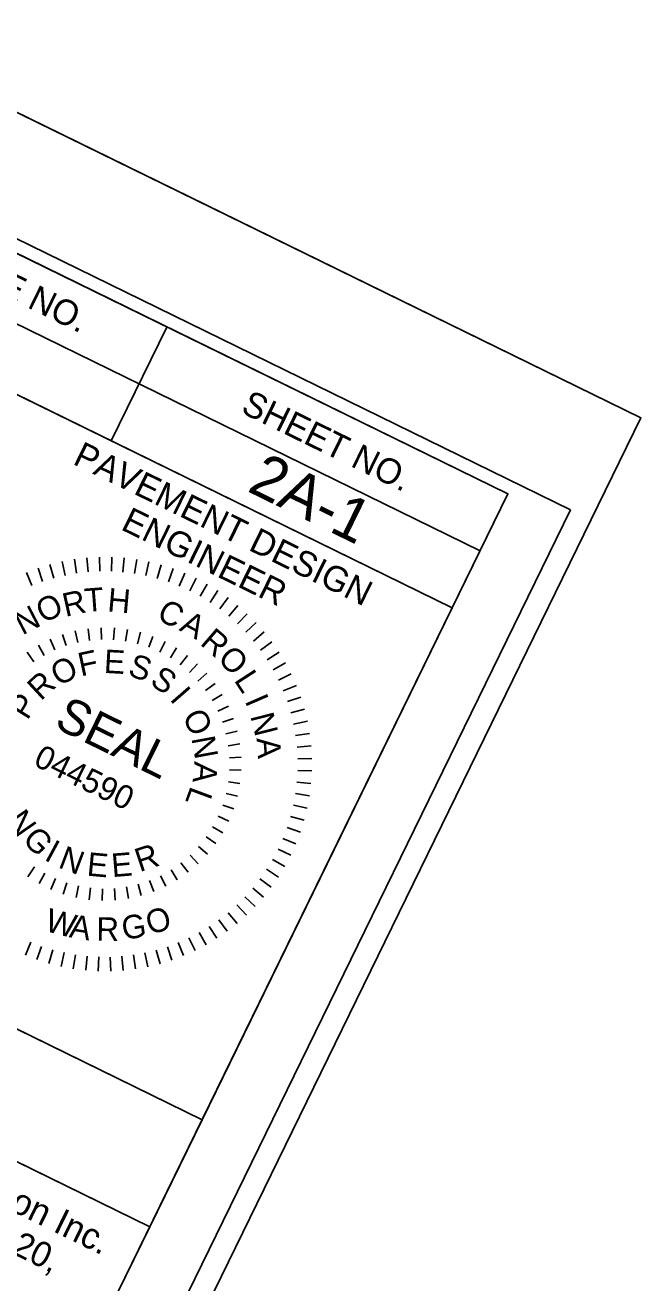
# Model space of a CAD drawing. Extents: x 1518247 to 1523638, y 635234 to 639927.
# Drawn here: x 1522799.6 to 1522921.3, y 639016 to 639264.3 of the extents above; entities that cross this region are included whole.
import ezdxf

# ---------------------------------------------------------------- set-up
doc = ezdxf.new("R2010")
doc.units = 0
for name, color, linetype in [('Default', 7, 'Continuous'), ('DTM TIN Hull White', 7, 'Continuous'), ('Prop Dimension Text', 7, 'Continuous'), ('Sheet Cutting Line CELL', 7, 'Continuous'), ('Sheet Plot Border Inside CELL', 7, 'Continuous'), ('Sheet Plot Border Outside CELL', 7, 'Continuous'), ('Sheet Sticker Exception Certification CELL', 7, 'Continuous'), ('Sheet Typical CELL', 7, 'Continuous')]:
    doc.layers.add(name, color=color, linetype=linetype)

msp = doc.modelspace()

# ---------------------------------------------------------------- linework, layer by layer
at = {"layer": 'Default'}
for points in [[(1522438.02, 638198.63), (1520925.25, 638938.49), (1521408.53, 639926.64), (1522921.3, 639186.78)], [(1522628.72, 639082.58), (1522808.42, 638994.69), (1522824.28, 639027.12), (1522644.58, 639115.01)]]:
    msp.add_lwpolyline(points, close=True, dxfattribs=at)
at = {"layer": 'DTM TIN Hull White'}
for p, q in [((1522806.95, 639158.42), (1522807.53, 639155.69)), ((1522809.38, 639158.86), (1522809.79, 639156.1)), ((1522811.83, 639159.15), (1522812.08, 639156.37)), ((1522814.3, 639159.29), (1522814.37, 639156.5)), ((1522816.76, 639159.28), (1522816.67, 639156.5)), ((1522819.23, 639159.13), (1522818.97, 639156.35)), ((1522821.68, 639158.83), (1522821.25, 639156.07)), ((1522824.11, 639158.37), (1522823.51, 639155.65)), ((1522799.88, 639156.23), (1522800.94, 639153.66)), ((1522802.19, 639157.1), (1522803.09, 639154.47)), ((1522804.55, 639157.83), (1522805.29, 639155.15)), ((1522826.5, 639157.77), (1522825.75, 639155.09)), ((1522828.86, 639157.03), (1522827.94, 639154.4)), ((1522831.16, 639156.15), (1522830.09, 639153.58)), ((1522833.41, 639155.13), (1522832.19, 639152.63)), ((1522835.6, 639153.98), (1522834.22, 639151.55)), ((1522837.7, 639152.69), (1522836.19, 639150.36)), ((1522839.73, 639151.29), (1522838.08, 639149.05)), ((1522841.67, 639149.76), (1522839.89, 639147.62)), ((1522843.52, 639148.12), (1522841.6, 639146.09)), ((1522845.26, 639146.37), (1522843.22, 639144.46)), ((1522807.01, 639144.02), (1522807.73, 639141.81)), ((1522809.52, 639144.72), (1522810.03, 639142.45)), ((1522812.08, 639145.16), (1522812.37, 639142.86)), ((1522814.68, 639145.36), (1522814.74, 639143.04)), ((1522817.28, 639145.31), (1522817.12, 639142.99)), ((1522819.87, 639145), (1522819.48, 639142.71)), ((1522822.41, 639144.45), (1522821.81, 639142.2)), ((1522824.89, 639143.65), (1522824.07, 639141.48)), ((1522846.89, 639144.51), (1522844.75, 639142.73)), ((1522802.25, 639141.93), (1522803.38, 639139.9)), ((1522804.58, 639143.09), (1522805.51, 639140.97)), ((1522827.28, 639142.62), (1522826.26, 639140.53)), ((1522826.26, 639140.53), (1522827.28, 639142.62)), ((1522829.56, 639141.36), (1522828.34, 639139.38)), ((1522848.41, 639142.57), (1522846.16, 639140.92)), ((1522800.04, 639140.55), (1522801.36, 639138.64)), ((1522831.7, 639139.89), (1522830.3, 639138.04)), ((1522849.81, 639140.53), (1522847.46, 639139.03)), ((1522851.08, 639138.41), (1522848.65, 639137.05)), ((1522833.7, 639138.22), (1522832.12, 639136.51)), ((1522835.53, 639136.36), (1522833.79, 639134.81)), ((1522852.22, 639136.23), (1522849.71, 639135.01)), ((1522837.16, 639134.34), (1522835.29, 639132.96)), ((1522853.23, 639133.97), (1522850.65, 639132.91)), ((1522838.6, 639132.16), (1522836.6, 639130.98)), ((1522854.09, 639131.66), (1522851.46, 639130.76)), ((1522839.81, 639129.86), (1522837.71, 639128.88)), ((1522854.82, 639129.3), (1522852.14, 639128.56)), ((1522840.8, 639127.46), (1522838.61, 639126.68)), ((1522855.41, 639126.9), (1522852.68, 639126.32)), ((1522841.55, 639124.96), (1522839.3, 639124.4)), ((1522855.85, 639124.47), (1522853.09, 639124.06)), ((1522842.07, 639122.41), (1522839.77, 639122.06)), ((1522856.14, 639122.02), (1522853.36, 639121.77)), ((1522842.32, 639119.82), (1522840, 639119.7)), ((1522856.28, 639119.55), (1522853.49, 639119.48)), ((1522842.33, 639117.22), (1522840.01, 639117.32)), ((1522856.27, 639117.08), (1522853.49, 639117.18)), ((1522842.09, 639114.62), (1522839.79, 639114.96)), ((1522856.12, 639114.62), (1522853.34, 639114.88)), ((1522841.6, 639112.07), (1522839.34, 639112.62)), ((1522855.82, 639112.17), (1522853.06, 639112.6)), ((1522840.86, 639109.57), (1522838.67, 639110.34)), ((1522855.36, 639109.74), (1522852.64, 639110.34)), ((1522839.89, 639107.16), (1522837.78, 639108.13)), ((1522854.77, 639107.35), (1522852.08, 639108.1)), ((1522835.43, 639104.09), (1522837.32, 639102.74)), ((1522838.69, 639104.85), (1522836.68, 639106.02)), ((1522853.14, 639102.69), (1522850.57, 639103.76)), ((1522854.02, 639104.99), (1522851.39, 639105.91)), ((1522835.64, 639100.63), (1522833.9, 639102.16)), ((1522852.12, 639100.44), (1522849.62, 639101.66)), ((1522831.85, 639097.08), (1522830.43, 639098.92)), ((1522833.83, 639098.76), (1522832.25, 639100.46)), ((1522850.97, 639098.25), (1522848.54, 639099.63)), ((1522800.19, 639096.21), (1522801.5, 639098.12)), ((1522802.41, 639094.84), (1522803.53, 639096.87)), ((1522827.44, 639094.32), (1522826.4, 639096.4)), ((1522829.71, 639095.59), (1522828.48, 639097.56)), ((1522849.68, 639096.14), (1522847.35, 639097.66)), ((1522804.74, 639093.69), (1522805.67, 639095.82)), ((1522807.18, 639092.78), (1522807.89, 639094.99)), ((1522809.7, 639092.1), (1522810.19, 639094.38)), ((1522812.26, 639091.67), (1522812.53, 639093.98)), ((1522814.86, 639091.5), (1522814.91, 639093.82)), ((1522817.46, 639091.57), (1522817.29, 639093.88)), ((1522820.05, 639091.89), (1522819.65, 639094.18)), ((1522822.59, 639092.46), (1522821.97, 639094.7)), ((1522825.06, 639093.27), (1522824.23, 639095.44)), ((1522846.75, 639092.18), (1522844.61, 639093.96)), ((1522848.28, 639094.11), (1522846.04, 639095.77)), ((1522845.11, 639090.33), (1522843.08, 639092.25)), ((1522841.5, 639086.96), (1522839.73, 639089.1)), ((1522843.36, 639088.59), (1522841.45, 639090.63)), ((1522837.52, 639084.04), (1522836.02, 639086.39)), ((1522839.56, 639085.44), (1522837.91, 639087.69)), ((1522833.22, 639081.63), (1522832, 639084.14)), ((1522835.4, 639082.77), (1522834.04, 639085.2)), ((1522799.68, 639080.71), (1522800.75, 639083.28)), ((1522801.98, 639079.83), (1522802.9, 639082.45)), ((1522804.34, 639079.08), (1522805.09, 639081.76)), ((1522826.29, 639079.03), (1522825.55, 639081.71)), ((1522828.65, 639079.76), (1522827.75, 639082.39)), ((1522830.96, 639080.62), (1522829.9, 639083.2)), ((1522806.73, 639078.49), (1522807.33, 639081.21)), ((1522809.16, 639078.03), (1522809.59, 639080.79)), ((1522811.61, 639077.73), (1522811.87, 639080.51)), ((1522814.07, 639077.58), (1522814.17, 639080.36)), ((1522816.54, 639077.57), (1522816.47, 639080.35)), ((1522819.01, 639077.71), (1522818.76, 639080.49)), ((1522821.46, 639078), (1522821.05, 639080.76)), ((1522823.89, 639078.44), (1522823.31, 639081.17))]:
    msp.add_line(p, q, dxfattribs=at)
at = {"layer": 'Sheet Cutting Line CELL'}
msp.add_line((1522921.3, 639186.78), (1521408.53, 639926.64), dxfattribs=at)
at = {"layer": 'Sheet Plot Border Inside CELL'}
msp.add_lwpolyline([(1522907.39, 639168.59), (1521410.35, 639900.76), (1520946.79, 638952.95), (1522443.84, 638220.77)], close=True, dxfattribs=at)
at = {"layer": 'Sheet Plot Border Outside CELL'}
msp.add_lwpolyline([(1522921.3, 639186.78), (1521408.53, 639926.64), (1520925.25, 638938.49), (1522438.02, 638198.63)], close=True, dxfattribs=at)
at = {"layer": 'Sheet Sticker Exception Certification CELL'}
for p, q in [((1522654.9, 639136.12), (1522834.6, 639048.23)), ((1522824.28, 639027.12), (1522644.58, 639115.01)), ((1522834.59, 639048.22), (1522824.27, 639027.11))]:
    msp.add_line(p, q, dxfattribs=at)
at = {"layer": 'Sheet Typical CELL'}
for p, q in [((1522709.82, 639248.41), (1522889.53, 639160.52)), ((1522827.65, 639204.7), (1522816.66, 639182.24))]:
    msp.add_line(p, q, dxfattribs=at)
for points in [[(1522895.04, 639171.79), (1521547.57, 639830.81), (1521086.25, 638887.58), (1522433.73, 638228.56)], [(1522715.33, 639259.68), (1522895.04, 639171.79), (1522884.04, 639149.29), (1522704.33, 639237.18)], [(1522794.21, 639193.22), (1522884.04, 639149.29), (1522834.61, 639048.23), (1522744.78, 639092.16)]]:
    msp.add_lwpolyline(points, close=True, dxfattribs=at)

# ---------------------------------------------------------------- texts
at = {"layer": 'Default'}
for s, height, p in [('Johnson, Mirmiran, & Thompson Inc.', 5.1112, (1522714.52, 639070.51)), ('2550 West Tyvola Road, Suite 120,', 4.9652, (1522711.22, 639063.77))]:
    msp.add_text(s, height=height, rotation=333.9377, dxfattribs=at).set_placement(p)
at = {"layer": 'DTM TIN Hull White'}
for s, height, rotation, p in [('T', 4.64, 4.3843, (1522811.55, 639148.43)), ('O', 4.64, 25.602, (1522803.21, 639146.15)), ('R', 4.64, 12.5453, (1522807.6, 639147.47)), ('H', 4.64, 354.9524, (1522815.79, 639148.6)), ('N', 4.64, 27.5614, (1522799.09, 639143.8)), ('C', 4.64, 331.2417, (1522825.4, 639147.21)), ('A', 4.64, 331.2417, (1522829.91, 639144.9)), ('R', 4.64, 319.2324, (1522834.02, 639142.12)), ('F', 4.64, 12.1253, (1522810.65, 639135.72)), ('E', 4.64, 356.8291, (1522815.13, 639136.44)), ('O', 4.64, 316.1756, (1522837.47, 639138.94)), ('O', 4.64, 27.4216, (1522806.23, 639133.72)), ('S', 4.64, 341.5328, (1522819.75, 639135.96)), ('R', 4.64, 42.7178, (1522802.74, 639130.78)), ('S', 4.64, 326.2366, (1522824.08, 639134.26)), ('L', 4.64, 303.0393, (1522840.8, 639135.01)), ('I', 4.64, 310.9403, (1522828.07, 639131.19)), ('P', 4.64, 58.0141, (1522800.09, 639126.96)), ('SEAL', 6.965, 333.8847, (1522805.13, 639125.8)), ('I', 4.64, 293.4638, (1522842.97, 639130.94)), ('O', 4.64, 295.6441, (1522830.63, 639127.92)), ('N', 4.64, 284.1693, (1522844.1, 639127.95)), ('N', 4.64, 280.3478, (1522832.47, 639123.56)), ('A', 4.64, 274.4018, (1522845.34, 639123.53)), ('044590', 4.64, 333.8847, (1522801.05, 639118.29)), ('A', 4.64, 265.0516, (1522833.09, 639119.03)), ('L', 4.64, 249.7554, (1522832.41, 639114.24)), ('N', 4.64, 304.8099, (1522795.8, 639107.33)), ('G', 4.64, 313.5761, (1522798.92, 639103.38)), ('I', 4.64, 331.6709, (1522803.23, 639099.61)), ('N', 4.64, 339.3006, (1522805.98, 639098.08)), ('R', 4.64, 18.4496, (1522822.26, 639097.07)), ('E', 4.64, 354.6926, (1522811.72, 639096.43)), ('E', 4.64, 4.6785, (1522816.86, 639096.11)), ('W', 4.64, 345.1793, (1522803.34, 639085.55)), ('G', 4.64, 8.3265, (1522819.06, 639083.72)), ('O', 4.64, 17.2091, (1522824.31, 639084.67)), ('A', 4.64, 350.5013, (1522808.19, 639084.28)), ('R', 4.64, 359.5039, (1522813.69, 639083.57))]:
    msp.add_text(s, height=height, rotation=rotation, dxfattribs=at).set_placement(p)
at = {"layer": 'Prop Dimension Text'}
msp.add_text('2A-1', height=8.643, rotation=333.8962, dxfattribs=at).set_placement((1522843.29, 639172.4))
at = {"layer": 'Sheet Typical CELL'}
for s, height, p in [('PROJECT REFERENCE NO.', 5.0001, (1522731.46, 639242.11)), ('SHEET NO.', 5, (1522842.04, 639187.92)), ('PAVEMENT DESIGN', 5.0001, (1522808.85, 639177.76)), ('ENGINEER', 5, (1522818.34, 639164.83))]:
    msp.add_text(s, height=height, rotation=333.9377, dxfattribs=at).set_placement(p)

doc.saveas('drawing.dxf')
